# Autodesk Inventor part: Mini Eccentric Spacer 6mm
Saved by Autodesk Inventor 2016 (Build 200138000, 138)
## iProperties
Created: 2016-01
Part Number: Mini Eccentric Spacer 6mm
Material: Generic
Document SubType Name: Modeling
Designer: John
Density: 1 g/cm^3
Appearance: Default
Author: John
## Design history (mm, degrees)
feature "CUT-REVOLVE1"
body "Solid1"
